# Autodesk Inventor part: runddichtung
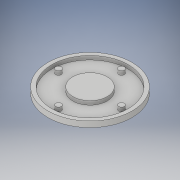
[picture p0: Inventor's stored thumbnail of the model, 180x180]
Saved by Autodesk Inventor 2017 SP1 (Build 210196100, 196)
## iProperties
Part Number: runddichtung
Material: Generisch
Document SubType Name: Modeling
Designer: haesner
Density: 1 g/cm^3
Appearance: Vorgabe
Part Number: runddichtung_3D-Druck
Author: haesner
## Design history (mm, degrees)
sketch "Skizze1"
  geometry: C1 r 22 at (0, 0); 1 further point
  constraints: 1 centre point, 1 coincident
  dimensions: "d0" = 44 diameter of C1
extrude "Extrusion1" new body sketch "Skizze1" distance "d1" = 3; taper "d2" = 0 deg
sketch "Skizze2"
  geometry: L1 (0, 16.5)-(-16.5, 0); L2 (-16.5, 0)-(0, -16.5); L3 (0, -16.5)-(16.5, 0); L4 (16.5, 0)-(0, 16.5); L5 (-30.8, 0)-(30.8, 0) reference; L6 (0, -30.8)-(0, 30.8) reference; C1 r 20 at (0, 0); C2 r 1.5 at (0, 16.5); C3 r 1.5 at (16.5, 0); C4 r 1.5 at (0, -16.5); C5 r 1.5 at (-16.5, 0); C6 r 9 at (0, 0); 1 further point
  constraints: 8 end point, 6 centre point, 6 coincident, 3 equal radius, 3 point on line, 2 parallel, 2 perpendicular
  dimensions: "d3" = 16.5 distance from line of L1.start L5; "d4" = 40 diameter of C1; "d5" = 3 diameter of C2; "d8" = 18 diameter of C6
extrude "Extrusion3" cut sketch "Skizze2" distance "d9" = 2; taper "d10" = 0 deg
node "Volumenkörper1"
